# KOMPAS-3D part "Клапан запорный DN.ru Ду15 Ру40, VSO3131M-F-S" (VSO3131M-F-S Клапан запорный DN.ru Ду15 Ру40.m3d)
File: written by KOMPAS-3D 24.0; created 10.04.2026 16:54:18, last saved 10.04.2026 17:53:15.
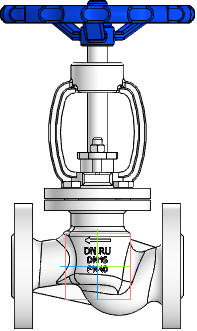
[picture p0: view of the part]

Document properties: Автор: R2D2; Полное имя файла: E:\Работа\Зайцев\VSO3131M-F-S Клапан запорный DN.ru Ду15-100 Ру40\DN15\VSO3131M-F-S Клапан запорный DN.ru Ду15 Ру40.m3d

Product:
- Body: Тело 4  | qty 1
    Масса: 4.60476
- Part/product: Клапан запорный DN.ru Ду15 Ру40  | designation VSO3131M-F-S
    Масса: 3.77
    Раздел спецификации: Прочие изделия
    Примечание: D090-02137

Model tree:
1. Операция без истории:5

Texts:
  Точка начала. Х
  Точка начала. Y
  Точка начала. Z
  VSO3131M-F-S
